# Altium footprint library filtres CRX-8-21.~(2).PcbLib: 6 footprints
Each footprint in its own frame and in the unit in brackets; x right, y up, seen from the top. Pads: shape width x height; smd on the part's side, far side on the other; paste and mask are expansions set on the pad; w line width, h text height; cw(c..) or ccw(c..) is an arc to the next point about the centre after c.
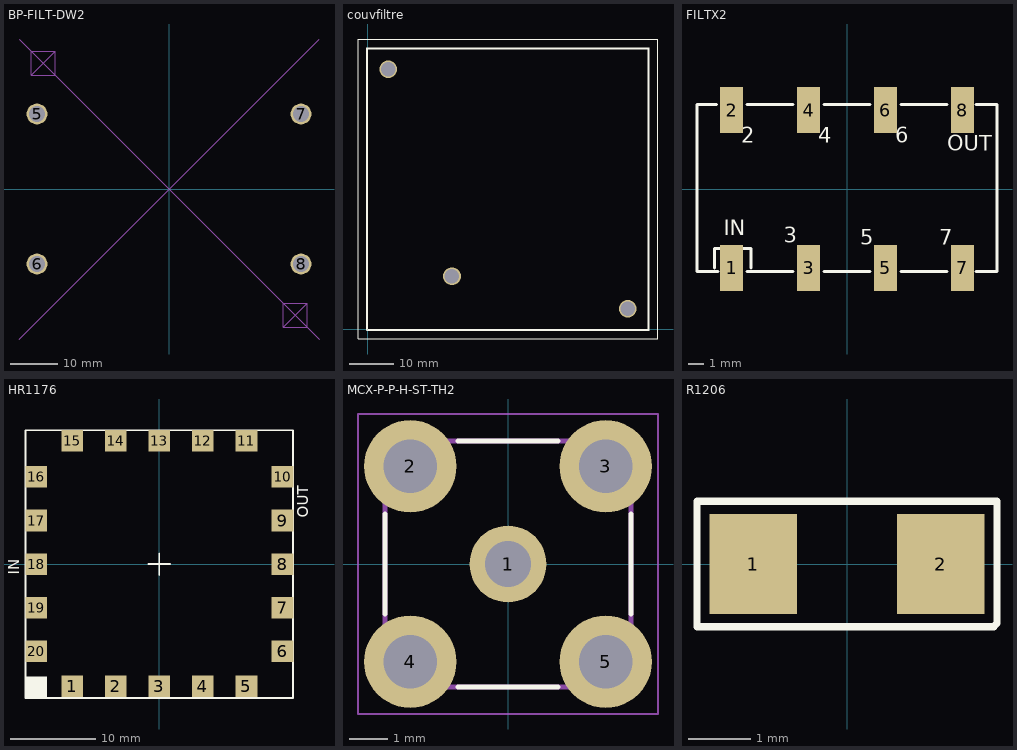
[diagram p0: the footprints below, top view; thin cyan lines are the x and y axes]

## BP-FILT-DW2 [mm]
pads (4):
  round 4.445 hole 3.3: 5(-27.94,15.875) 6(-27.94,-15.875) 7(27.94,15.875) 8(27.94,-15.875)
Mechanical 4:
  lines w0.203: -31.75,-31.75 31.75,31.75 ; -31.75,31.75 31.75,-31.75 ; -29.21,24.13 -29.21,29.21 -24.13,29.21 ; -29.21,24.13 -24.13,24.13 -24.13,29.21 ; -29.21,24.13 -24.13,29.21 ; 24.13,-29.21 24.13,-24.13 29.21,-24.13 ; 24.13,-29.21 29.21,-29.21 29.21,-24.13 ; 24.13,-29.21 29.21,-24.13

## couvfiltre [mil]
via 179.92,2320.08 diameter 157.48 hole 129.92
via 750,470.08 diameter 157.48 hole 129.92
via 2320.08,179.92 diameter 157.48 hole 129.92
Top Overlay:
  lines w3.94: -88.58,-88.58 -88.58,2588.58 2588.58,2588.58 2588.58,-88.58 -88.58,-88.58 ; -9.84,-9.84 2509.84,-9.84 2509.84,2509.84 -9.84,2509.84 -9.84,-9.84 ; 0,0 2500,0 2500,2500 0,2500 0,0

## FILTX2 [mil]
pads (8):
  rect 60x120 smd: 1(-300,-205) 2(-300,205) 3(-100,-205) 4(-100,205) 5(100,-205) 6(100,205) 7(300,-205) 8(300,205)
Top Overlay:
  lines w8: -345,-205 -345,-155 -250,-155 -250,-205 ; -340,220 -390,220 -390,-215 -335,-215 ; -260,-215 -140,-215 ; -260,220 -140,220 ; -60,-215 60,-215 ; -60,220 60,220 ; 140,-215 260,-215 ; 140,220 260,220 ; 335,-215 390,-215 390,220 335,220
  text "2" at -275,120 h40
  text "4" at -75,120 h40
  text "6" at 125,120 h40
  text "3" at -165,-140 h40
  text "5" at 35,-145 h40
  text "7" at 240,-145 h40
  text "IN" at -320,-120 h40
  text "OUT" at 260,100 h40
Top Paste:
  region: -273,-262 -273,-148 -327,-148 -327,-262
  region: -73,-262 -73,-148 -127,-148 -127,-262
  region: 327,-262 327,-148 273,-148 273,-262
  region: 127,-262 127,-148 73,-148 73,-262
  region: 327,148 327,262 273,262 273,148
  region: 127,148 127,262 73,262 73,148
  region: -73,148 -73,262 -127,262 -127,148
  region: -273,148 -273,262 -327,262 -327,148

## HR1176 [mil]
pads (20):
  rect 100x100 smd: 1(-404,-566) 2(-202,-566) 3(0,-566) 4(202,-566) 5(404,-566) 6(571,-404) 7(571,-202) 8(571,0) 9(571,202) 10(571,404) 11(404,571) 12(202,571) 13(0,571) 14(-202,571) 15(-404,571) 16(-571,404) 17(-571,202) 18(-571,0) 19(-571,-202) 20(-571,-404)
Top Overlay:
  region: -520,-620 -520,-520 -620,-520 -620,-620
  lines w8: -50,0 50,0 ; 0,-50 0,50 ; -620,-620 620,-620 620,620 -620,620 -620,-620
  text "OUT" at 690,215 h50
  text "IN" at -650,-50 h50
Top Paste:
  region: -523,-48 -523,48 -619,48 -619,-48
  region: -523,-250 -523,-154 -619,-154 -619,-250
  region: -523,-452 -523,-356 -619,-356 -619,-452
  region: -356,-614 -356,-518 -452,-518 -452,-614
  region: -154,-614 -154,-518 -250,-518 -250,-614
  region: 48,-614 48,-518 -48,-518 -48,-614
  region: 250,-614 250,-518 154,-518 154,-614
  region: 452,-614 452,-518 356,-518 356,-614
  region: 619,-452 619,-356 523,-356 523,-452
  region: 619,-250 619,-154 523,-154 523,-250
  region: 619,-48 619,48 523,48 523,-48
  region: 619,154 619,250 523,250 523,154
  region: 619,356 619,452 523,452 523,356
  region: 452,523 452,619 356,619 356,523
  region: 250,523 250,619 154,619 154,523
  region: 48,523 48,619 -48,619 -48,523
  region: -153,522 -153,618 -249,618 -249,522
  region: -356,523 -356,619 -452,619 -452,523
  region: -523,356 -523,452 -619,452 -619,356
  region: -523,154 -523,250 -619,250 -619,154

## MCX-P-P-H-ST-TH2 [mm]
pads (5):
  round 2 hole 1.2: 1(0,0)
  round 2.4 hole 1.4: 2(-2.54,2.54) 3(2.54,2.54) 4(-2.54,-2.54) 5(2.54,-2.54)
Top Overlay:
  lines w0.127: -3.2,-1.3 -3.2,1.3 ; -1.3,-3.2 1.3,-3.2 ; -1.3,3.2 1.3,3.2 ; 3.2,-1.3 3.2,1.3
Mechanical 4:
  lines w0.127: -3.2,-3.2 -3.2,3.2 ; -3.2,-3.2 3.2,-3.2 ; -3.2,-3.2 -3.2,3.2 ; -3.2,-3.2 3.2,-3.2 ; -3.2,3.2 3.2,3.2 ; -3.2,3.2 3.2,3.2 ; 3.2,-3.2 3.2,3.2 ; 3.2,-3.2 3.2,3.2
Mechanical 16:
  lines w0.05: -3.9,-3.9 -3.9,3.9 3.9,3.9 3.9,-3.9 -3.9,-3.9
3D body "MCX-P-P-H-ST-TH2.stp": height 11.2, standoff -1.8, extent -3,-3 3,3

## R1206 [mm]
pads (2):
  rect 1.4x1.6 smd mask+0.05: 1(-1.5,0) 2(1.5,0)
Top Overlay:
  lines w0.12: -2.4,-1 2.35,-1 2.4,-0.95 2.4,0.95 2.4,1 -2.4,1 -2.4,-1
3D body "User Library-1206 SMD Resistor.step": height 1, standoff 0, extent -1.6,-0.8 1.6,0.8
